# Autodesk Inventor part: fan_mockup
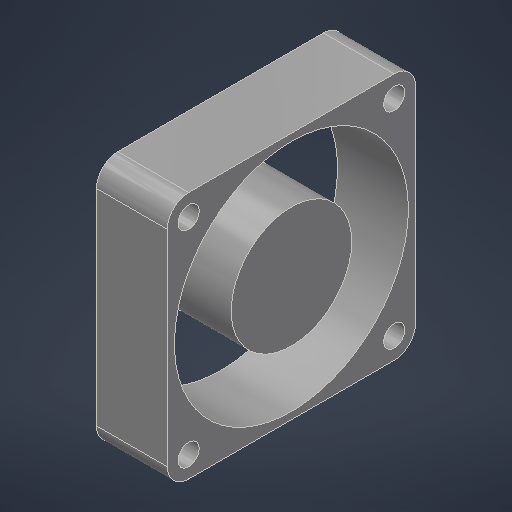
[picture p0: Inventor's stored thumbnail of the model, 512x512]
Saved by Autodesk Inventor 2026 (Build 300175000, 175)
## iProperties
Created: 2025-05
Part Number: fan_mockup
Material: 1.0037 S235JR
Document SubType Name: Modeling
Designer: BennF
Density: 7.85 g/cm^3
Appearance: Stahl
Author: BennF
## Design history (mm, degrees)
sketch "Sketch2"
  geometry: L1 (-14.5, 17.5)-(14.5, 17.5); L2 (17.5, 14.5)-(17.5, -14.5); L3 (14.5, -17.5)-(-14.5, -17.5); L4 (-17.5, -14.5)-(-17.5, 14.5); C1 r 8.5 at (0, 0); C2 r 16.5 at (0, 0); C3 r 1.5 at (-14.5, 14.5); C4 r 1.5 at (14.5, 14.5); C5 r 1.5 at (14.5, -14.5); C6 r 1.5 at (-14.5, -14.5); A1 r 3 centre (-14.5, 14.5) between (-14.5, 17.5) and (-17.5, 14.5); A2 r 3 centre (14.5, 14.5) between (17.5, 14.5) and (14.5, 17.5); A3 r 3 centre (14.5, -14.5) between (14.5, -17.5) and (17.5, -14.5); A4 r 3 centre (-14.5, -14.5) between (-17.5, -14.5) and (-14.5, -17.5); 5 further points
  constraints: 10 centre point, 8 end point, 8 point on circle, 8 tangent, 6 coincident, 6 equal radius, 4 point on line, 2 midpoint, 2 parallel, 2 perpendicular, 1 horizontal, 1 horizontal alignment, 1 vertical alignment
  dimensions: "d0" = 35 distance of point (-17.5, 17.5) point (17.5, 17.5); "d1" = 3 radius of A1; "d2" = 33 diameter of C2; "d3" = 17 diameter of C1; "d4" = 3 diameter of C3
extrude "Extrusion1" new body sketch "Sketch2" distance "d5" = 10; taper "d6" = 0 deg
body "Solid1"
